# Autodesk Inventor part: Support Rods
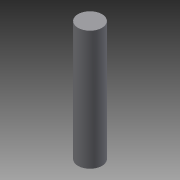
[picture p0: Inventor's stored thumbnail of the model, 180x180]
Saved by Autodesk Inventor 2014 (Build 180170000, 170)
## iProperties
Created: 2013-11
Part Number: Support Rods
Material: Generic
Document SubType Name: Modeling
Designer: 603839
Density: 1 g/cm^3
Appearance: Default
Mass: 8.04398 g
Surface Area: 27.8689 cm^2
Volume: 8.04398 cm^3
Author: 603839
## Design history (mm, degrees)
sketch "Sketch1"
  geometry: C1 r 6.35 at (0, 0); 1 further point
  constraints: 1 centre point, 1 coincident
  dimensions: "d0" = 12.7 diameter of C1
extrude "Extrusion1" new body sketch "Sketch1" distance "d1" = 101.6; taper "d2" = 0 deg
sketch "Sketch2"
  geometry: C1 r 6.35 at (0, 0) reference
extrude "Extrusion2" cut sketch "Sketch2" distance "d3" = 38.1; taper "d4" = 0 deg
body "Solid1"
